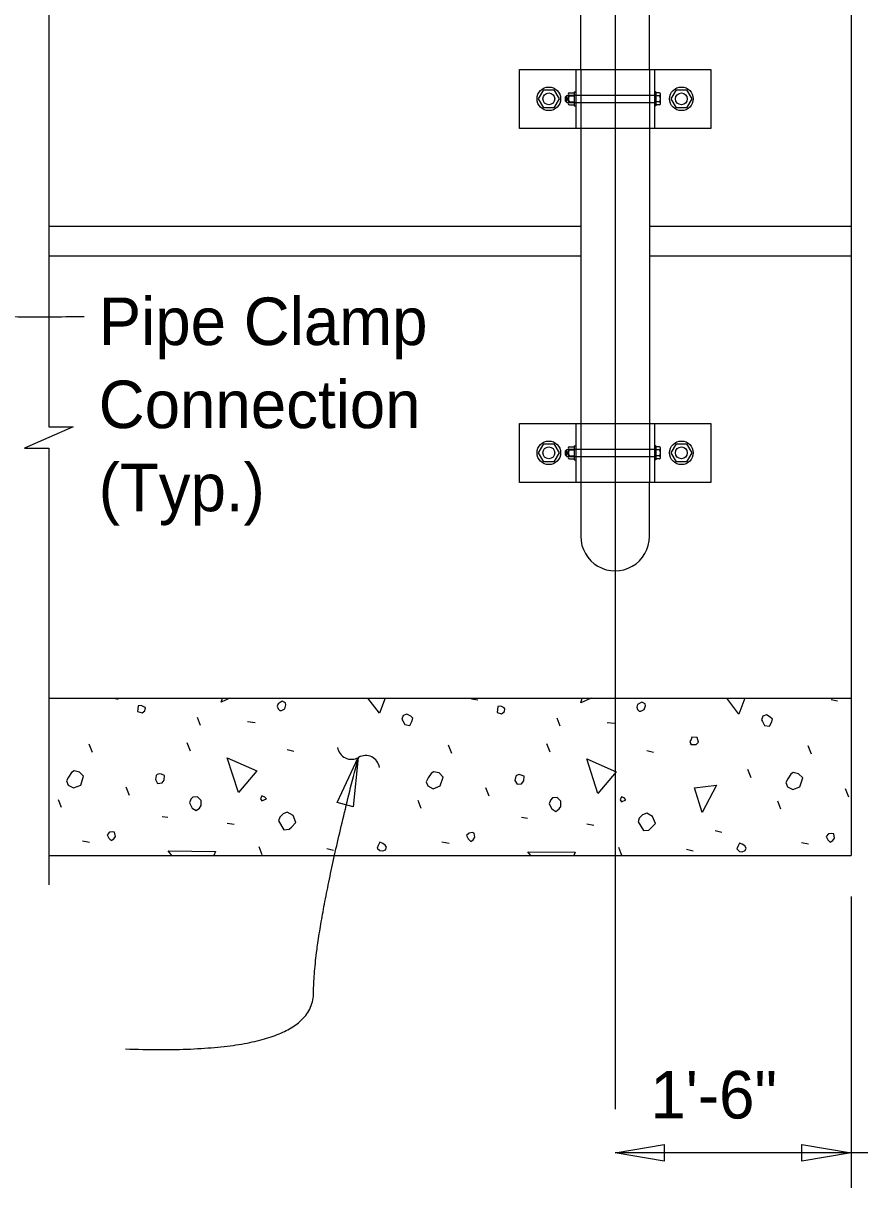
# Model space of a CAD drawing. Extents: x 0 to 41.2, y 0 to 26.
# Drawn here: x 23.735 to 27.279, y 12.062 to 16.996 of the extents above; entities that cross this region are included whole.
import ezdxf

# ---------------------------------------------------------------- set-up
doc = ezdxf.new("R2010")
doc.units = 0
for name, color, linetype in [('CL_Major', 7, 'Continuous'), ('Dimension', 7, 'Continuous'), ('Miscellaneous', 7, 'Continuous'), ('SteelMisc', 7, 'Continuous'), ('SteelMisc_h', 7, 'Continuous'), ('SupstrConc', 7, 'Continuous'), ('TextStructures', 7, 'Continuous')]:
    doc.layers.add(name, color=color, linetype=linetype)

msp = doc.modelspace()

# ---------------------------------------------------------------- linework, layer by layer
at = {"layer": 'CL_Major'}
msp.add_line((26.2429, 25.5043), (26.2429, 12.3953), dxfattribs=at)
at = {"layer": 'Dimension'}
for p, q in [((27.2429, 13.2961), (27.2429, 12.062)), ((28.5763, 12.21), (26.2429, 12.21))]:
    msp.add_line(p, q, dxfattribs=at)
msp.add_lwpolyline([(23.8431, 17.1361), (23.8431, 15.2855), (23.9464, 15.2855), (23.8431, 15.2405), (23.7397, 15.1955), (23.8431, 15.1955), (23.8431, 13.3448)], dxfattribs=at)
for points in [[(25.1546, 13.8857), (25.1324, 13.6757), (25.0644, 13.6947)], [(26.2429, 12.2101), (26.4512, 12.2454), (26.4512, 12.1748)], [(27.2429, 12.2101), (27.0347, 12.1748), (27.0347, 12.2454)]]:
    msp.add_lwpolyline(points, close=True, dxfattribs=at)
for centre, start, end in [((25.1255, 13.9368), 188.4294, 300.1567), ((25.1854, 13.8337), 8.4294, 120.1567)]:
    msp.add_arc(centre, 0.0596, start, end, dxfattribs=at)
for points in [[(23.9932, 15.7529), (23.0399, 15.7236), (23.3618, 16.2556), (23.4433, 16.5898), (22.9335, 16.6682), (22.6122, 16.6783)], [(24.1685, 12.6502), (24.964, 12.6205), (24.9656, 13.1567), (25.1547, 13.8855)]]:
    msp.add_open_spline(points, degree=2, dxfattribs=at)
at = {"layer": 'Miscellaneous'}
for p, q in [((26.0354, 16.6691), (26.0354, 16.6812)), ((26.0411, 16.6691), (26.0411, 16.6812)), ((26.0354, 15.1691), (26.0354, 15.1812)), ((26.0411, 15.1691), (26.0411, 15.1812)), ((24.1186, 14.1361), (24.1373, 14.1324)), ((25.6346, 14.1341), (25.6611, 14.1288)), ((27.1584, 14.1306), (27.185, 14.1253)), ((24.4856, 14.021), (24.4732, 14.0546)), ((24.6853, 14.0369), (24.7172, 14.0334)), ((26.0094, 14.0175), (25.997, 14.051)), ((26.2092, 14.0334), (26.241, 14.0298)), ((24.0277, 13.9061), (24.0136, 13.9414)), ((24.4432, 13.9114), (24.429, 13.9467)), ((24.8533, 13.9185), (24.8816, 13.9114)), ((25.5515, 13.9026), (25.5374, 13.9379)), ((25.967, 13.9079), (25.9528, 13.9432)), ((26.3771, 13.9149), (26.4054, 13.9079)), ((27.0754, 13.899), (27.0612, 13.9344)), ((26.819, 13.7983), (26.8049, 13.8336)), ((24.1851, 13.724), (24.1709, 13.7594)), ((25.7089, 13.7205), (25.6947, 13.7558)), ((27.2327, 13.7169), (27.2185, 13.7523)), ((23.8969, 13.6727), (23.8845, 13.7063)), ((25.4207, 13.6692), (25.4084, 13.7028)), ((26.9445, 13.6657), (26.9322, 13.6993)), ((24.3229, 13.6356), (24.3477, 13.6321)), ((25.8468, 13.6321), (25.8715, 13.6286)), ((24.5987, 13.6073), (24.6288, 13.602)), ((26.1225, 13.6038), (26.1526, 13.5985)), ((26.667, 13.5755), (26.6953, 13.5684)), ((23.9853, 13.5313), (24.0154, 13.526)), ((25.5091, 13.5278), (25.5392, 13.5225)), ((27.0329, 13.5243), (27.063, 13.5189)), ((24.7472, 13.473), (24.7348, 13.5066)), ((25.0212, 13.4995), (25.0495, 13.4924)), ((26.271, 13.4695), (26.2587, 13.503)), ((26.545, 13.496), (26.5733, 13.4889))]:
    msp.add_line(p, q, dxfattribs=at)
for points in [[(24.574, 14.12), (24.5789, 14.1361)], [(24.6099, 14.1361), (24.574, 14.12)], [(24.8215, 14.0846), (24.8285, 14.0846), (24.8427, 14.0917), (24.848, 14.1076), (24.8462, 14.1165), (24.8321, 14.1235), (24.8144, 14.1129), (24.8109, 14.1023), (24.8144, 14.0917), (24.8215, 14.0846)], [(25.244, 14.0723), (25.1954, 14.1361)], [(25.2678, 14.1361), (25.244, 14.0723)], [(26.0978, 14.1165), (26.1038, 14.1361)], [(26.1416, 14.1361), (26.0978, 14.1165)], [(26.3453, 14.0811), (26.3523, 14.0811), (26.3665, 14.0882), (26.3718, 14.1041), (26.37, 14.1129), (26.3559, 14.12), (26.3382, 14.1094), (26.3347, 14.0988), (26.3382, 14.0882), (26.3453, 14.0811)], [(26.7678, 14.0687), (26.7165, 14.1361)], [(26.793, 14.1361), (26.7678, 14.0687)], [(24.2186, 14.0793), (24.2381, 14.074), (24.2505, 14.0829), (24.2522, 14.0952), (24.2487, 14.0988), (24.2346, 14.1058), (24.2222, 14.1041), (24.2204, 14.0917), (24.2186, 14.0793)], [(25.3429, 14.0404), (25.3518, 14.0245), (25.373, 14.021), (25.3818, 14.0369), (25.3854, 14.051), (25.3765, 14.0599), (25.3606, 14.0687), (25.3447, 14.0634), (25.3394, 14.0475), (25.3429, 14.0404)], [(25.7425, 14.0758), (25.7619, 14.0705), (25.7743, 14.0793), (25.7761, 14.0917), (25.7725, 14.0952), (25.7584, 14.1023), (25.746, 14.1005), (25.7442, 14.0882), (25.7425, 14.0758)], [(26.8668, 14.0369), (26.8756, 14.021), (26.8968, 14.0175), (26.9057, 14.0334), (26.9092, 14.0475), (26.9004, 14.0564), (26.8844, 14.0652), (26.8685, 14.0599), (26.8632, 14.044), (26.8668, 14.0369)], [(26.5645, 13.9397), (26.5857, 13.9397), (26.5963, 13.9503), (26.591, 13.9697), (26.568, 13.9715), (26.5645, 13.9609), (26.5592, 13.9521), (26.5645, 13.9397), (26.5609, 13.9432)], [(24.6464, 13.7364), (24.5987, 13.8831), (24.7242, 13.8283), (24.6464, 13.7364)], [(26.1703, 13.7328), (26.1225, 13.8796), (26.248, 13.8248), (26.1703, 13.7328)], [(23.9252, 13.7682), (23.9482, 13.7558), (23.9782, 13.7682), (23.9906, 13.8053), (23.9729, 13.823), (23.9499, 13.8283), (23.9393, 13.8212), (23.927, 13.8018), (23.9181, 13.7859), (23.9252, 13.7682)], [(24.2947, 13.7912), (24.3035, 13.7753), (24.3229, 13.777), (24.3318, 13.7894), (24.3336, 13.8089), (24.3212, 13.8142), (24.3123, 13.8159), (24.3017, 13.8124), (24.2982, 13.8089), (24.2947, 13.7912)], [(25.449, 13.7647), (25.472, 13.7523), (25.502, 13.7647), (25.5144, 13.8018), (25.4967, 13.8195), (25.4738, 13.8248), (25.4632, 13.8177), (25.4508, 13.7983), (25.4419, 13.7823), (25.449, 13.7647)], [(26.9728, 13.7611), (26.9958, 13.7488), (27.0259, 13.7611), (27.0382, 13.7983), (27.0206, 13.8159), (26.9976, 13.8212), (26.987, 13.8142), (26.9746, 13.7947), (26.9658, 13.7788), (26.9728, 13.7611)], [(25.8185, 13.7876), (25.8273, 13.7717), (25.8468, 13.7735), (25.8556, 13.7859), (25.8574, 13.8053), (25.845, 13.8106), (25.8362, 13.8124), (25.8255, 13.8089), (25.822, 13.8053), (25.8185, 13.7876)], [(26.6122, 13.6515), (26.5786, 13.7558), (26.6723, 13.7682), (26.6122, 13.6515)], [(24.4396, 13.6922), (24.4502, 13.671), (24.4679, 13.6604), (24.482, 13.671), (24.4891, 13.6816), (24.4891, 13.7028), (24.4732, 13.7187), (24.4538, 13.7169), (24.4449, 13.7081), (24.4396, 13.6922)], [(24.7454, 13.701), (24.7649, 13.7099), (24.7578, 13.7169), (24.7454, 13.7222), (24.7401, 13.7099), (24.7454, 13.701)], [(26.2693, 13.6975), (26.2887, 13.7063), (26.2816, 13.7134), (26.2693, 13.7187), (26.264, 13.7063), (26.2693, 13.6975)], [(25.9634, 13.6887), (25.974, 13.6674), (25.9917, 13.6568), (26.0059, 13.6674), (26.0129, 13.678), (26.0129, 13.6993), (25.997, 13.7152), (25.9776, 13.7134), (25.9687, 13.7046), (25.9634, 13.6887)], [(24.8162, 13.6162), (24.8391, 13.5791), (24.8621, 13.5808), (24.871, 13.5897), (24.8904, 13.6091), (24.878, 13.6392), (24.8533, 13.6533), (24.8356, 13.6462), (24.8215, 13.6321), (24.8162, 13.6162)], [(26.34, 13.6126), (26.3629, 13.5755), (26.3859, 13.5773), (26.3948, 13.5861), (26.4142, 13.6056), (26.4018, 13.6356), (26.3771, 13.6498), (26.3594, 13.6427), (26.3453, 13.6286), (26.34, 13.6126)], [(24.0967, 13.5437), (24.1073, 13.5331), (24.1179, 13.5402), (24.125, 13.5508), (24.1214, 13.5684), (24.1126, 13.5702), (24.1002, 13.5684), (24.0896, 13.5578), (24.0967, 13.5437)], [(25.2457, 13.4907), (25.2581, 13.4889), (25.2705, 13.4942), (25.274, 13.5048), (25.2687, 13.5136), (25.2581, 13.5207), (25.2457, 13.526), (25.2386, 13.5119), (25.2351, 13.5013), (25.2457, 13.4907)], [(25.6205, 13.5402), (25.6311, 13.5296), (25.6417, 13.5366), (25.6488, 13.5472), (25.6452, 13.5649), (25.6364, 13.5667), (25.624, 13.5649), (25.6134, 13.5543), (25.6205, 13.5402)], [(26.7695, 13.4871), (26.7819, 13.4854), (26.7943, 13.4907), (26.7978, 13.5013), (26.7925, 13.5101), (26.7819, 13.5172), (26.7695, 13.5225), (26.7625, 13.5083), (26.7589, 13.4977), (26.7695, 13.4871)], [(27.1443, 13.5366), (27.1549, 13.526), (27.1655, 13.5331), (27.1726, 13.5437), (27.1691, 13.5614), (27.1602, 13.5631), (27.1478, 13.5614), (27.1372, 13.5508), (27.1443, 13.5366)], [(24.3642, 13.4695), (24.3495, 13.4889), (24.5492, 13.4871), (24.5426, 13.4695)], [(25.8854, 13.4695), (25.8733, 13.4854), (26.073, 13.4836), (26.0678, 13.4695)]]:
    msp.add_lwpolyline(points, dxfattribs=at)
at = {"layer": 'SteelMisc'}
for p, q in [((26.0971, 16.801), (26.0971, 17.2769)), ((26.3888, 16.801), (26.3888, 17.2769)), ((25.837, 16.801), (26.6489, 16.801)), ((25.837, 16.551), (25.837, 16.801)), ((26.0763, 16.801), (26.0763, 16.551)), ((26.4096, 16.801), (26.4096, 16.551)), ((26.6489, 16.801), (26.6489, 16.551)), ((26.0326, 16.684), (26.0382, 16.6906)), ((26.0326, 16.6663), (26.0326, 16.684)), ((26.0382, 16.6906), (26.0447, 16.6906)), ((26.0382, 16.6607), (26.0382, 16.6906)), ((26.0447, 16.6939), (26.0447, 16.6582)), ((26.0494, 16.689), (26.0697, 16.689)), ((26.0496, 16.702), (26.0697, 16.702)), ((26.0697, 16.7063), (26.0697, 16.6457)), ((26.0697, 16.7063), (26.0763, 16.7063)), ((26.0697, 16.702), (26.0697, 16.65)), ((26.4159, 16.7063), (26.4098, 16.7063)), ((26.4159, 16.7063), (26.4159, 16.6457)), ((26.4306, 16.702), (26.4159, 16.702)), ((26.4307, 16.689), (26.4159, 16.689)), ((26.4357, 16.6566), (26.4357, 16.6955)), ((26.0326, 16.6663), (26.0382, 16.6607)), ((26.0382, 16.6607), (26.0447, 16.6607)), ((26.0494, 16.6631), (26.0697, 16.6631)), ((26.0497, 16.65), (26.0697, 16.65)), ((26.0697, 16.6457), (26.0763, 16.6457)), ((26.4159, 16.6457), (26.4098, 16.6457)), ((26.4307, 16.663), (26.4159, 16.663)), ((26.4306, 16.65), (26.4159, 16.65)), ((26.6489, 16.551), (25.837, 16.551)), ((26.0971, 16.551), (26.0971, 15.301)), ((26.3888, 16.551), (26.3888, 15.301)), ((25.837, 15.301), (26.6489, 15.301)), ((25.837, 15.051), (25.837, 15.301)), ((26.0763, 15.301), (26.0763, 15.051)), ((26.4096, 15.301), (26.4096, 15.051)), ((26.6489, 15.301), (26.6489, 15.051)), ((26.0496, 15.202), (26.0697, 15.202)), ((26.0697, 15.2063), (26.0697, 15.1457)), ((26.0697, 15.2063), (26.0763, 15.2063)), ((26.0697, 15.202), (26.0697, 15.15)), ((26.4159, 15.2063), (26.4098, 15.2063)), ((26.4159, 15.2063), (26.4159, 15.1457)), ((26.4306, 15.202), (26.4159, 15.202)), ((26.0326, 15.184), (26.0382, 15.1906)), ((26.0326, 15.1663), (26.0326, 15.184)), ((26.0326, 15.1663), (26.0382, 15.1607)), ((26.0382, 15.1906), (26.0447, 15.1906)), ((26.0382, 15.1607), (26.0382, 15.1906)), ((26.0382, 15.1607), (26.0447, 15.1607)), ((26.0447, 15.1939), (26.0447, 15.1582)), ((26.0494, 15.189), (26.0697, 15.189)), ((26.0494, 15.1631), (26.0697, 15.1631)), ((26.0497, 15.15), (26.0697, 15.15)), ((26.4307, 15.189), (26.4159, 15.189)), ((26.4307, 15.163), (26.4159, 15.163)), ((26.4306, 15.15), (26.4159, 15.15)), ((26.4357, 15.1566), (26.4357, 15.1955)), ((26.0697, 15.1457), (26.0763, 15.1457)), ((26.4159, 15.1457), (26.4098, 15.1457)), ((26.6489, 15.051), (25.837, 15.051)), ((26.097, 15.051), (26.097, 14.8218)), ((26.3887, 14.8218), (26.3887, 15.051))]:
    msp.add_line(p, q, dxfattribs=at)
for points in [[(25.9403, 16.7135), (25.9836, 16.7135), (26.0053, 16.676), (25.9836, 16.6385), (25.9403, 16.6385), (25.9186, 16.676)], [(26.5023, 16.7135), (26.5456, 16.7135), (26.5673, 16.676), (26.5456, 16.6385), (26.5023, 16.6385), (26.4806, 16.676)], [(25.9403, 15.2135), (25.9836, 15.2135), (26.0053, 15.176), (25.9836, 15.1385), (25.9403, 15.1385), (25.9186, 15.176)], [(26.5023, 15.2135), (26.5456, 15.2135), (26.5673, 15.176), (26.5456, 15.1385), (26.5023, 15.1385), (26.4806, 15.176)]]:
    msp.add_lwpolyline(points, close=True, dxfattribs=at)
for centre, radius in [((25.962, 16.676), 0.05), ((25.962, 16.676), 0.025), ((26.5239, 16.676), 0.05), ((26.5239, 16.676), 0.025), ((25.962, 15.176), 0.05), ((25.962, 15.176), 0.025), ((26.5239, 15.176), 0.05), ((26.5239, 15.176), 0.025)]:
    msp.add_circle(centre, radius, dxfattribs=at)
for centre, radius, start, end in [((26.0513, 16.6955), 0.00674, 104.4891, 254.1889), ((26.0642, 16.676), 0.0196, 138.628, 221.372), ((26.4289, 16.6955), 0.00673, 285.7823, 75.5404), ((26.416, 16.676), 0.0196, 318.628, 41.372), ((26.0513, 16.6565), 0.00673, 105.7823, 255.5404), ((26.4289, 16.6565), 0.00674, 284.4891, 74.1889), ((26.0513, 15.1955), 0.00674, 104.4891, 254.1889), ((26.4289, 15.1955), 0.00673, 285.7823, 75.5404), ((26.0642, 15.176), 0.0196, 138.628, 221.372), ((26.0513, 15.1565), 0.00673, 105.7823, 255.5404), ((26.4289, 15.1565), 0.00674, 284.4891, 74.1889), ((26.416, 15.176), 0.0196, 318.628, 41.372)]:
    msp.add_arc(centre, radius, start, end, dxfattribs=at)
msp.add_ellipse((26.2429, 14.8218), major_axis=(0, 0.1458), ratio=0.999499, start_param=1.570796, end_param=4.712389, dxfattribs=at)
at = {"layer": 'SteelMisc_h'}
for p, q in [((26.0971, 16.801), (26.0971, 16.551)), ((26.3888, 16.801), (26.3888, 16.551)), ((26.4096, 16.6906), (26.0447, 16.6906)), ((26.0447, 16.6607), (26.4096, 16.6607)), ((26.0971, 15.301), (26.0971, 15.051)), ((26.3888, 15.301), (26.3888, 15.051)), ((26.4096, 15.1906), (26.0447, 15.1906)), ((26.0447, 15.1607), (26.4096, 15.1607))]:
    msp.add_line(p, q, dxfattribs=at)
at = {"layer": 'SupstrConc'}
for p, q in [((27.2429, 17.1361), (27.2429, 13.4695)), ((23.8431, 16.1361), (26.0971, 16.1361)), ((26.3888, 16.1361), (27.2428, 16.1361)), ((23.8431, 16.0111), (26.0971, 16.0111)), ((26.3888, 16.0111), (27.2428, 16.0111)), ((23.8431, 14.1361), (27.2429, 14.1361)), ((23.8431, 13.4695), (27.2429, 13.4695))]:
    msp.add_line(p, q, dxfattribs=at)

# ---------------------------------------------------------------- texts
at = {"layer": 'Dimension'}
for s, p in [('Pipe Clamp ', (24.0545, 15.6326)), ('Connection ', (24.0545, 15.2806)), ('(Typ.)', (24.0545, 14.9286))]:
    msp.add_text(s, height=0.2016, dxfattribs=at).set_placement(p)
at = {"layer": 'TextStructures'}
msp.add_text('1\'-6"', height=0.2016, dxfattribs=at).set_placement((26.3923, 12.3553))

doc.saveas('drawing.dxf')
